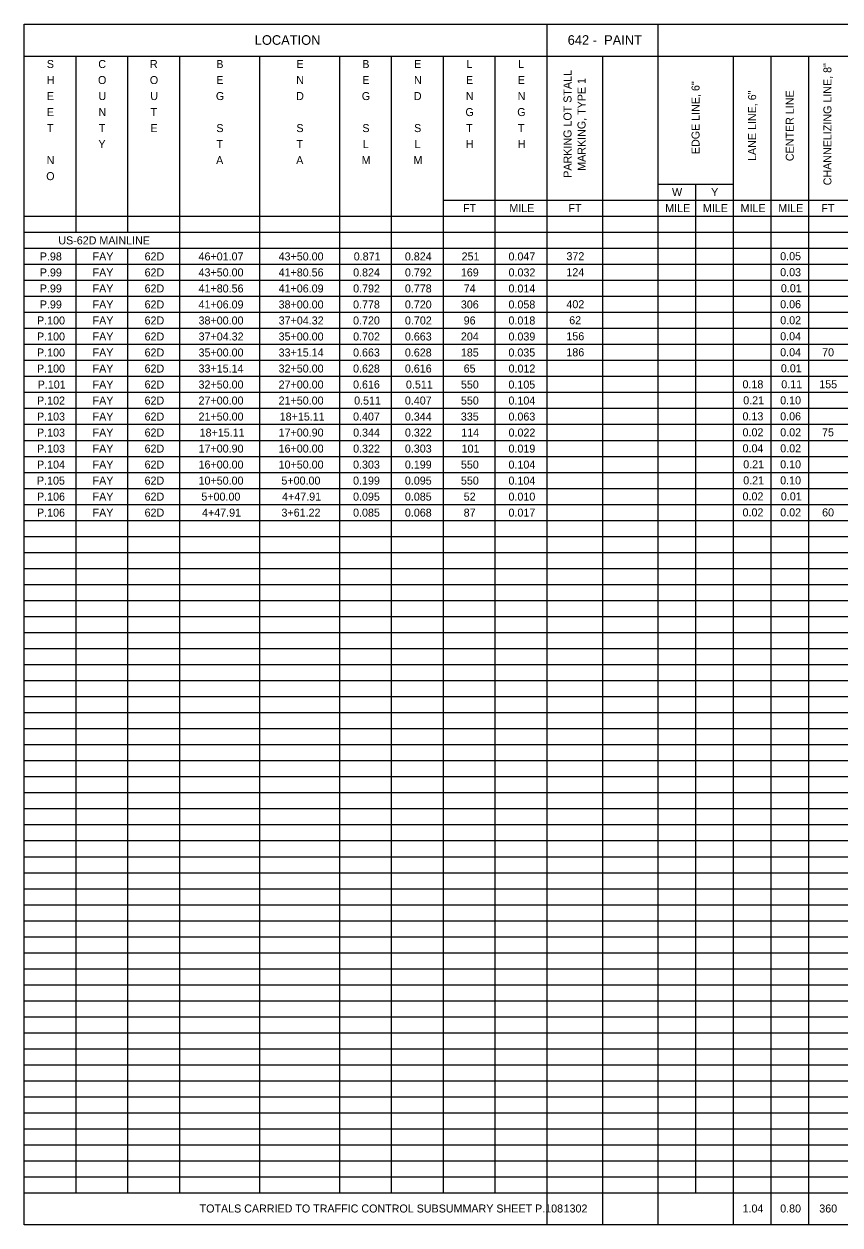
# Model space of a CAD drawing. Extents: x 12522 to 13018, y 1124 to 1902.
# Drawn here: x 12873.15 to 12887.42, y 1732.23 to 1753.23 of the extents above; entities that cross this region are included whole.
import ezdxf

# ---------------------------------------------------------------- set-up
doc = ezdxf.new("R2010")
doc.units = 0
for name, color, linetype in [('SC_Scratch1', 7, 'Continuous'), ('SH_Data', 7, 'Continuous'), ('SH_Text', 7, 'Continuous')]:
    doc.layers.add(name, color=color, linetype=linetype)

msp = doc.modelspace()

# ---------------------------------------------------------------- linework, layer by layer
at = {"layer": 'SC_Scratch1'}
msp.add_lwpolyline([(12873.148, 1753.227), (12903.648, 1753.227), (12903.648, 1732.227), (12873.148, 1732.227)], close=True, dxfattribs=at)
at = {"layer": 'SH_Data'}
for p, q in [((12882.289, 1753.227), (12882.289, 1732.243)), ((12884.233, 1753.227), (12884.233, 1732.243)), ((12873.148, 1752.667), (12903.635, 1752.667)), ((12874.054, 1752.667), (12874.054, 1749.587)), ((12874.96, 1752.667), (12874.96, 1749.587)), ((12875.865, 1752.667), (12875.865, 1732.787)), ((12877.265, 1752.667), (12877.265, 1732.787)), ((12878.665, 1752.667), (12878.665, 1732.787)), ((12879.571, 1752.667), (12879.571, 1732.787)), ((12880.477, 1752.667), (12880.477, 1732.787)), ((12881.383, 1752.667), (12881.383, 1732.787)), ((12883.261, 1752.667), (12883.261, 1732.243)), ((12885.55, 1752.667), (12885.55, 1732.243)), ((12886.209, 1752.667), (12886.209, 1732.243)), ((12886.868, 1752.667), (12886.868, 1732.243)), ((12884.233, 1750.427), (12885.55, 1750.427)), ((12884.891, 1750.427), (12884.891, 1732.787)), ((12880.477, 1750.147), (12903.635, 1750.147)), ((12873.148, 1749.867), (12903.635, 1749.867)), ((12873.148, 1749.587), (12903.635, 1749.587)), ((12873.148, 1749.307), (12903.635, 1749.307)), ((12874.054, 1749.307), (12874.054, 1732.787)), ((12874.96, 1749.307), (12874.96, 1732.787)), ((12873.148, 1749.027), (12903.635, 1749.027)), ((12873.148, 1748.747), (12903.635, 1748.747)), ((12873.148, 1748.467), (12903.635, 1748.467)), ((12873.148, 1748.187), (12903.635, 1748.187)), ((12873.148, 1747.907), (12903.635, 1747.907)), ((12873.148, 1747.627), (12903.635, 1747.627)), ((12873.148, 1747.347), (12903.635, 1747.347)), ((12873.148, 1747.067), (12903.635, 1747.067)), ((12873.148, 1746.787), (12903.635, 1746.787)), ((12873.148, 1746.507), (12903.635, 1746.507)), ((12873.148, 1746.227), (12903.635, 1746.227)), ((12873.148, 1745.947), (12903.635, 1745.947)), ((12873.148, 1745.667), (12903.635, 1745.667)), ((12873.148, 1745.387), (12903.635, 1745.387)), ((12873.148, 1745.107), (12903.635, 1745.107)), ((12873.148, 1744.827), (12903.635, 1744.827)), ((12873.148, 1744.547), (12903.635, 1744.547)), ((12873.148, 1744.267), (12903.635, 1744.267)), ((12873.148, 1743.987), (12903.635, 1743.987)), ((12873.148, 1743.707), (12903.635, 1743.707)), ((12873.148, 1743.427), (12903.635, 1743.427)), ((12873.148, 1743.147), (12903.635, 1743.147)), ((12873.148, 1742.867), (12903.635, 1742.867)), ((12873.148, 1742.587), (12903.635, 1742.587)), ((12873.148, 1742.307), (12903.635, 1742.307)), ((12873.148, 1742.027), (12903.635, 1742.027)), ((12873.148, 1741.747), (12903.635, 1741.747)), ((12873.148, 1741.467), (12903.635, 1741.467)), ((12873.148, 1741.187), (12903.635, 1741.187)), ((12873.148, 1740.907), (12903.635, 1740.907)), ((12873.148, 1740.627), (12903.635, 1740.627)), ((12873.148, 1740.347), (12903.635, 1740.347)), ((12873.148, 1740.067), (12903.635, 1740.067)), ((12873.148, 1739.787), (12903.635, 1739.787)), ((12873.148, 1739.507), (12903.635, 1739.507)), ((12873.148, 1739.227), (12903.635, 1739.227)), ((12873.148, 1738.947), (12903.635, 1738.947)), ((12873.148, 1738.667), (12903.635, 1738.667)), ((12873.148, 1738.387), (12903.635, 1738.387)), ((12873.148, 1738.107), (12903.635, 1738.107)), ((12873.148, 1737.827), (12903.635, 1737.827)), ((12873.148, 1737.547), (12903.635, 1737.547)), ((12873.148, 1737.267), (12903.635, 1737.267)), ((12873.148, 1736.987), (12903.635, 1736.987)), ((12873.148, 1736.707), (12903.635, 1736.707)), ((12873.148, 1736.427), (12903.635, 1736.427)), ((12873.148, 1736.147), (12903.635, 1736.147)), ((12873.148, 1735.867), (12903.635, 1735.867)), ((12873.148, 1735.587), (12903.635, 1735.587)), ((12873.148, 1735.307), (12903.635, 1735.307)), ((12873.148, 1735.027), (12903.635, 1735.027)), ((12873.148, 1734.747), (12903.635, 1734.747)), ((12873.148, 1734.467), (12903.635, 1734.467)), ((12873.148, 1734.187), (12903.635, 1734.187)), ((12873.148, 1733.907), (12903.635, 1733.907)), ((12873.148, 1733.627), (12903.635, 1733.627)), ((12873.148, 1733.347), (12903.635, 1733.347)), ((12873.148, 1733.067), (12903.635, 1733.067)), ((12873.148, 1732.787), (12903.635, 1732.787))]:
    msp.add_line(p, q, dxfattribs=at)

# ---------------------------------------------------------------- texts
at = {"layer": 'SH_Text'}
for s, height, p in [('LOCATION', 0.168, (12877.183, 1752.863)), ('642 -  PAINT', 0.168, (12882.655, 1752.863)), ('S', 0.14, (12873.547, 1752.457)), ('C', 0.14, (12874.447, 1752.457)), ('R', 0.14, (12875.35, 1752.457)), ('B', 0.14, (12876.511, 1752.457)), ('E', 0.14, (12877.911, 1752.457)), ('B', 0.14, (12879.064, 1752.457)), ('E', 0.14, (12879.97, 1752.457)), ('L', 0.14, (12880.884, 1752.457)), ('L', 0.14, (12881.79, 1752.457)), ('H', 0.14, (12873.544, 1752.177)), ('O', 0.14, (12874.442, 1752.177)), ('O', 0.14, (12875.348, 1752.177)), ('E', 0.14, (12876.511, 1752.177)), ('N', 0.14, (12877.909, 1752.177)), ('E', 0.14, (12879.064, 1752.177)), ('N', 0.14, (12879.968, 1752.177)), ('E', 0.14, (12880.876, 1752.177)), ('E', 0.14, (12881.782, 1752.177)), ('E', 0.14, (12873.547, 1751.897)), ('U', 0.14, (12874.45, 1751.897)), ('U', 0.14, (12875.356, 1751.897)), ('G', 0.14, (12876.503, 1751.897)), ('D', 0.14, (12877.907, 1751.897)), ('G', 0.14, (12879.055, 1751.897)), ('D', 0.14, (12879.965, 1751.897)), ('N', 0.14, (12880.874, 1751.897)), ('N', 0.14, (12881.78, 1751.897)), ('E', 0.14, (12873.547, 1751.617)), ('N', 0.14, (12874.45, 1751.617)), ('T', 0.14, (12875.361, 1751.617)), ('G', 0.14, (12880.867, 1751.617)), ('G', 0.14, (12881.773, 1751.617)), ('T', 0.14, (12873.549, 1751.337)), ('T', 0.14, (12874.455, 1751.337)), ('E', 0.14, (12875.359, 1751.337)), ('S', 0.14, (12876.511, 1751.337)), ('S', 0.14, (12877.911, 1751.337)), ('S', 0.14, (12879.064, 1751.337)), ('S', 0.14, (12879.97, 1751.337)), ('T', 0.14, (12880.878, 1751.337)), ('T', 0.14, (12881.784, 1751.337)), ('Y', 0.14, (12874.449, 1751.057)), ('T', 0.14, (12876.513, 1751.057)), ('T', 0.14, (12877.913, 1751.057)), ('L', 0.14, (12879.073, 1751.057)), ('L', 0.14, (12879.978, 1751.057)), ('H', 0.14, (12880.874, 1751.057)), ('H', 0.14, (12881.78, 1751.057)), ('N', 0.14, (12873.544, 1750.777)), ('A', 0.14, (12876.507, 1750.777)), ('A', 0.14, (12877.907, 1750.777)), ('M', 0.14, (12879.052, 1750.777)), ('M', 0.14, (12879.958, 1750.777)), ('O', 0.14, (12873.536, 1750.497)), ('W', 0.14, (12884.48, 1750.217)), ('Y', 0.14, (12885.163, 1750.217)), ('FT', 0.14, (12880.824, 1749.937)), ('MILE', 0.14, (12881.635, 1749.937)), ('FT', 0.14, (12882.669, 1749.937)), ('MILE', 0.14, (12884.361, 1749.937)), ('MILE', 0.14, (12885.02, 1749.937)), ('MILE', 0.14, (12885.679, 1749.937)), ('MILE', 0.14, (12886.338, 1749.937)), ('FT', 0.14, (12887.091, 1749.937)), ('US-62D MAINLINE', 0.14, (12873.748, 1749.373)), ('P.98', 0.14, (12873.424, 1749.093)), ('FAY', 0.14, (12874.347, 1749.093)), ('62D', 0.14, (12875.256, 1749.093)), ('46+01.07', 0.14, (12876.2, 1749.093)), ('43+50.00', 0.14, (12877.6, 1749.093)), ('0.871', 0.14, (12878.914, 1749.093)), ('0.824', 0.14, (12879.808, 1749.093)), ('251', 0.14, (12880.8, 1749.093)), ('0.047', 0.14, (12881.62, 1749.093)), ('372', 0.14, (12882.633, 1749.097)), ('0.05', 0.14, (12886.371, 1749.097)), ('P.99', 0.14, (12873.424, 1748.813)), ('FAY', 0.14, (12874.347, 1748.813)), ('62D', 0.14, (12875.256, 1748.813)), ('43+50.00', 0.14, (12876.2, 1748.813)), ('41+80.56', 0.14, (12877.6, 1748.813)), ('0.824', 0.14, (12878.903, 1748.813)), ('0.792', 0.14, (12879.809, 1748.813)), ('169', 0.14, (12880.787, 1748.813)), ('0.032', 0.14, (12881.621, 1748.813)), ('124', 0.14, (12882.632, 1748.817)), ('0.03', 0.14, (12886.371, 1748.817)), ('P.99', 0.14, (12873.424, 1748.533)), ('FAY', 0.14, (12874.347, 1748.533)), ('62D', 0.14, (12875.256, 1748.533)), ('41+80.56', 0.14, (12876.2, 1748.533)), ('41+06.09', 0.14, (12877.6, 1748.533)), ('0.792', 0.14, (12878.903, 1748.533)), ('0.778', 0.14, (12879.808, 1748.533)), ('74', 0.14, (12880.837, 1748.533)), ('0.014', 0.14, (12881.62, 1748.533)), ('0.01', 0.14, (12886.383, 1748.537)), ('P.99', 0.14, (12873.424, 1748.253)), ('FAY', 0.14, (12874.347, 1748.253)), ('62D', 0.14, (12875.256, 1748.253)), ('41+06.09', 0.14, (12876.2, 1748.253)), ('38+00.00', 0.14, (12877.6, 1748.253)), ('0.778', 0.14, (12878.902, 1748.253)), ('0.720', 0.14, (12879.808, 1748.253)), ('306', 0.14, (12880.787, 1748.253)), ('0.058', 0.14, (12881.62, 1748.253)), ('402', 0.14, (12882.633, 1748.257)), ('0.06', 0.14, (12886.371, 1748.257)), ('P.100', 0.14, (12873.375, 1747.973)), ('FAY', 0.14, (12874.347, 1747.973)), ('62D', 0.14, (12875.256, 1747.973)), ('38+00.00', 0.14, (12876.2, 1747.973)), ('37+04.32', 0.14, (12877.601, 1747.973)), ('0.720', 0.14, (12878.902, 1747.973)), ('0.702', 0.14, (12879.809, 1747.973)), ('96', 0.14, (12880.836, 1747.973)), ('0.018', 0.14, (12881.62, 1747.973)), ('62', 0.14, (12882.682, 1747.977)), ('0.02', 0.14, (12886.372, 1747.977)), ('P.100', 0.14, (12873.375, 1747.693)), ('FAY', 0.14, (12874.347, 1747.693)), ('62D', 0.14, (12875.256, 1747.693)), ('37+04.32', 0.14, (12876.201, 1747.693)), ('35+00.00', 0.14, (12877.6, 1747.693)), ('0.702', 0.14, (12878.903, 1747.693)), ('0.663', 0.14, (12879.808, 1747.693)), ('204', 0.14, (12880.788, 1747.693)), ('0.039', 0.14, (12881.62, 1747.693)), ('156', 0.14, (12882.632, 1747.697)), ('0.04', 0.14, (12886.371, 1747.697)), ('P.100', 0.14, (12873.375, 1747.413)), ('FAY', 0.14, (12874.347, 1747.413)), ('62D', 0.14, (12875.256, 1747.413)), ('35+00.00', 0.14, (12876.2, 1747.413)), ('33+15.14', 0.14, (12877.6, 1747.413)), ('0.663', 0.14, (12878.902, 1747.413)), ('0.628', 0.14, (12879.808, 1747.413)), ('185', 0.14, (12880.787, 1747.413)), ('0.035', 0.14, (12881.619, 1747.413)), ('186', 0.14, (12882.632, 1747.417)), ('0.04', 0.14, (12886.371, 1747.417)), ('70', 0.14, (12887.104, 1747.417)), ('P.100', 0.14, (12873.375, 1747.133)), ('FAY', 0.14, (12874.347, 1747.133)), ('62D', 0.14, (12875.256, 1747.133)), ('33+15.14', 0.14, (12876.2, 1747.133)), ('32+50.00', 0.14, (12877.6, 1747.133)), ('0.628', 0.14, (12878.902, 1747.133)), ('0.616', 0.14, (12879.808, 1747.133)), ('65', 0.14, (12880.836, 1747.133)), ('0.012', 0.14, (12881.621, 1747.133)), ('0.01', 0.14, (12886.383, 1747.137)), ('P.101', 0.14, (12873.387, 1746.853)), ('FAY', 0.14, (12874.347, 1746.853)), ('62D', 0.14, (12875.256, 1746.853)), ('32+50.00', 0.14, (12876.2, 1746.853)), ('27+00.00', 0.14, (12877.6, 1746.853)), ('0.616', 0.14, (12878.902, 1746.853)), ('0.511', 0.14, (12879.827, 1746.853)), ('550', 0.14, (12880.788, 1746.853)), ('0.105', 0.14, (12881.619, 1746.853)), ('0.18', 0.14, (12885.712, 1746.857)), ('0.11', 0.14, (12886.39, 1746.857)), ('155', 0.14, (12887.054, 1746.857)), ('P.102', 0.14, (12873.375, 1746.573)), ('FAY', 0.14, (12874.347, 1746.573)), ('62D', 0.14, (12875.256, 1746.573)), ('27+00.00', 0.14, (12876.2, 1746.573)), ('21+50.00', 0.14, (12877.6, 1746.573)), ('0.511', 0.14, (12878.921, 1746.573)), ('0.407', 0.14, (12879.808, 1746.573)), ('550', 0.14, (12880.788, 1746.573)), ('0.104', 0.14, (12881.62, 1746.573)), ('0.21', 0.14, (12885.725, 1746.577)), ('0.10', 0.14, (12886.371, 1746.577)), ('P.103', 0.14, (12873.375, 1746.293)), ('FAY', 0.14, (12874.347, 1746.293)), ('62D', 0.14, (12875.256, 1746.293)), ('21+50.00', 0.14, (12876.2, 1746.293)), ('18+15.11', 0.14, (12877.619, 1746.293)), ('0.407', 0.14, (12878.902, 1746.293)), ('0.344', 0.14, (12879.808, 1746.293)), ('335', 0.14, (12880.787, 1746.293)), ('0.063', 0.14, (12881.62, 1746.293)), ('0.13', 0.14, (12885.712, 1746.297)), ('0.06', 0.14, (12886.371, 1746.297)), ('P.103', 0.14, (12873.375, 1746.013)), ('FAY', 0.14, (12874.347, 1746.013)), ('62D', 0.14, (12875.256, 1746.013)), ('18+15.11', 0.14, (12876.219, 1746.013)), ('17+00.90', 0.14, (12877.6, 1746.013)), ('0.344', 0.14, (12878.903, 1746.013)), ('0.322', 0.14, (12879.809, 1746.013)), ('114', 0.14, (12880.794, 1746.013)), ('0.022', 0.14, (12881.621, 1746.013)), ('0.02', 0.14, (12885.713, 1746.017)), ('0.02', 0.14, (12886.372, 1746.017)), ('75', 0.14, (12887.103, 1746.017)), ('P.103', 0.14, (12873.375, 1745.733)), ('FAY', 0.14, (12874.347, 1745.733)), ('62D', 0.14, (12875.256, 1745.733)), ('17+00.90', 0.14, (12876.2, 1745.733)), ('16+00.00', 0.14, (12877.6, 1745.733)), ('0.322', 0.14, (12878.903, 1745.733)), ('0.303', 0.14, (12879.808, 1745.733)), ('101', 0.14, (12880.8, 1745.733)), ('0.019', 0.14, (12881.62, 1745.733)), ('0.04', 0.14, (12885.713, 1745.737)), ('0.02', 0.14, (12886.372, 1745.737)), ('P.104', 0.14, (12873.375, 1745.453)), ('FAY', 0.14, (12874.347, 1745.453)), ('62D', 0.14, (12875.256, 1745.453)), ('16+00.00', 0.14, (12876.2, 1745.453)), ('10+50.00', 0.14, (12877.6, 1745.453)), ('0.303', 0.14, (12878.902, 1745.453)), ('0.199', 0.14, (12879.808, 1745.453)), ('550', 0.14, (12880.788, 1745.453)), ('0.104', 0.14, (12881.62, 1745.453)), ('0.21', 0.14, (12885.725, 1745.457)), ('0.10', 0.14, (12886.371, 1745.457)), ('P.105', 0.14, (12873.374, 1745.173)), ('FAY', 0.14, (12874.347, 1745.173)), ('62D', 0.14, (12875.256, 1745.173)), ('10+50.00', 0.14, (12876.2, 1745.173)), ('5+00.00', 0.14, (12877.649, 1745.173)), ('0.199', 0.14, (12878.902, 1745.173)), ('0.095', 0.14, (12879.808, 1745.173)), ('550', 0.14, (12880.788, 1745.173)), ('0.104', 0.14, (12881.62, 1745.173)), ('0.21', 0.14, (12885.725, 1745.177)), ('0.10', 0.14, (12886.371, 1745.177)), ('P.106', 0.14, (12873.375, 1744.893)), ('FAY', 0.14, (12874.347, 1744.893)), ('62D', 0.14, (12875.256, 1744.893)), ('5+00.00', 0.14, (12876.249, 1744.893)), ('4+47.91', 0.14, (12877.661, 1744.893)), ('0.095', 0.14, (12878.902, 1744.893)), ('0.085', 0.14, (12879.808, 1744.893)), ('52', 0.14, (12880.837, 1744.893)), ('0.010', 0.14, (12881.62, 1744.893)), ('0.02', 0.14, (12885.713, 1744.897)), ('0.01', 0.14, (12886.383, 1744.897)), ('P.106', 0.14, (12873.375, 1744.613)), ('FAY', 0.14, (12874.347, 1744.613)), ('62D', 0.14, (12875.256, 1744.613)), ('4+47.91', 0.14, (12876.261, 1744.613)), ('3+61.22', 0.14, (12877.65, 1744.613)), ('0.085', 0.14, (12878.902, 1744.613)), ('0.068', 0.14, (12879.808, 1744.613)), ('87', 0.14, (12880.836, 1744.613)), ('0.017', 0.14, (12881.62, 1744.613)), ('0.02', 0.14, (12885.713, 1744.617)), ('0.02', 0.14, (12886.372, 1744.617)), ('60', 0.14, (12887.104, 1744.617)), ('TOTALS CARRIED TO TRAFFIC CONTROL SUBSUMMARY SHEET P.108', 0.14, (12876.218, 1732.445)), ('1302', 0.14, (12882.584, 1732.445)), ('1.04', 0.14, (12885.713, 1732.445)), ('0.80', 0.14, (12886.371, 1732.445)), ('360', 0.14, (12887.055, 1732.445))]:
    msp.add_text(s, height=height, dxfattribs=at).set_placement(p)
for s, p in [('CHANNELIZING LINE, 8"', (12887.267, 1750.406)), ('PARKING LOT STALL ', (12882.722, 1750.539)), ('MARKING, TYPE 1', (12882.967, 1750.66)), ('EDGE LINE, 6"', (12884.961, 1750.952)), ('LANE LINE, 6"', (12885.95, 1750.832)), ('CENTER LINE', (12886.608, 1750.829))]:
    msp.add_text(s, height=0.14, rotation=90, dxfattribs=at).set_placement(p)

doc.saveas('drawing.dxf')
